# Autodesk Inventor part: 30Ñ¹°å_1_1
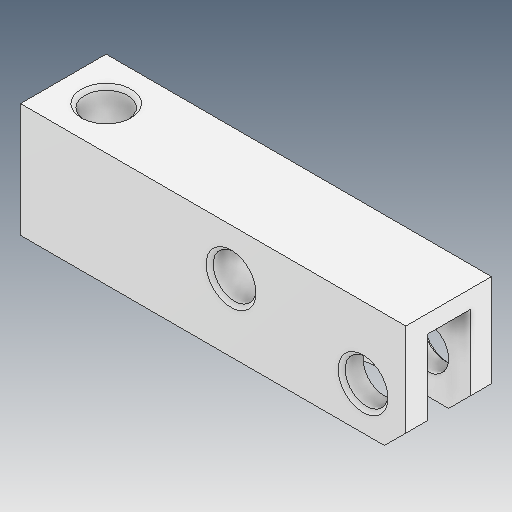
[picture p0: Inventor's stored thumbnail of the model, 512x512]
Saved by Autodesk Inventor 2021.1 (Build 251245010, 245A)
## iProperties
Created: 2021-05
Part Number: 30Ñ¹°å_1_1
Material: Ogólny
Document SubType Name: Modeling
Designer: user
Density: 1 g/cm^3
Appearance: Domyślna
Author: user
Revision Number: ÈÎºÎ
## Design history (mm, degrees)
feature "ÊäÈë1"
node "Bryła1"
